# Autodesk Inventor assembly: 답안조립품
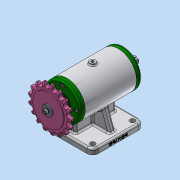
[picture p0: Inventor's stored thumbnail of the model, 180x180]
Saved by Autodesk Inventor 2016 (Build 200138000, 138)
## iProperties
Created: 2019-06
Part Number: 답안조립품
Material: 일반
Document SubType Name: Assembly
Designer: Administrator
Author: Administrator
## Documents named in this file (11)
- C:\Users\Administrator\Desktop\490604V1016\답안조립품.iam
- C:\Users\Administrator\Desktop\490604V1016\본체.ipt
- C:\Users\Administrator\Desktop\490604V1016\축.ipt
- C:\Users\Administrator\Desktop\490604V1016\베어링 6203.ipt
- C:\Users\Administrator\Desktop\490604V1016\커버.ipt
- C:\Users\Administrator\Desktop\490604V1016\오일 실 17 30 5.ipt
- C:\Users\Administrator\Desktop\490604V1016\볼트 M4.ipt
- C:\Users\Administrator\Desktop\490604V1016\키 4x4x12.ipt
- C:\Users\Administrator\Desktop\490604V1016\스프로킷.ipt
- C:\Users\Administrator\Desktop\490604V1016\평와셔.ipt
- C:\Users\Administrator\Desktop\490604V1016\스프링와셔.ipt
